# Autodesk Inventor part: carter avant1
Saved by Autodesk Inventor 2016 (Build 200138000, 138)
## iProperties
Created: 2013-10
Part Number: carter avant1
Material: Générique
Document SubType Name: Modeling
Designer: Bruno
Density: 1 g/cm^3
Appearance: Par défaut
Author: Bruno
Sending System: SolidWorks 2013
Last Author: christophe
Last Saved: 2014-02-15
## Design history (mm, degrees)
feature "Enlèv. mat.-Extru.6"
node "Solide1"
